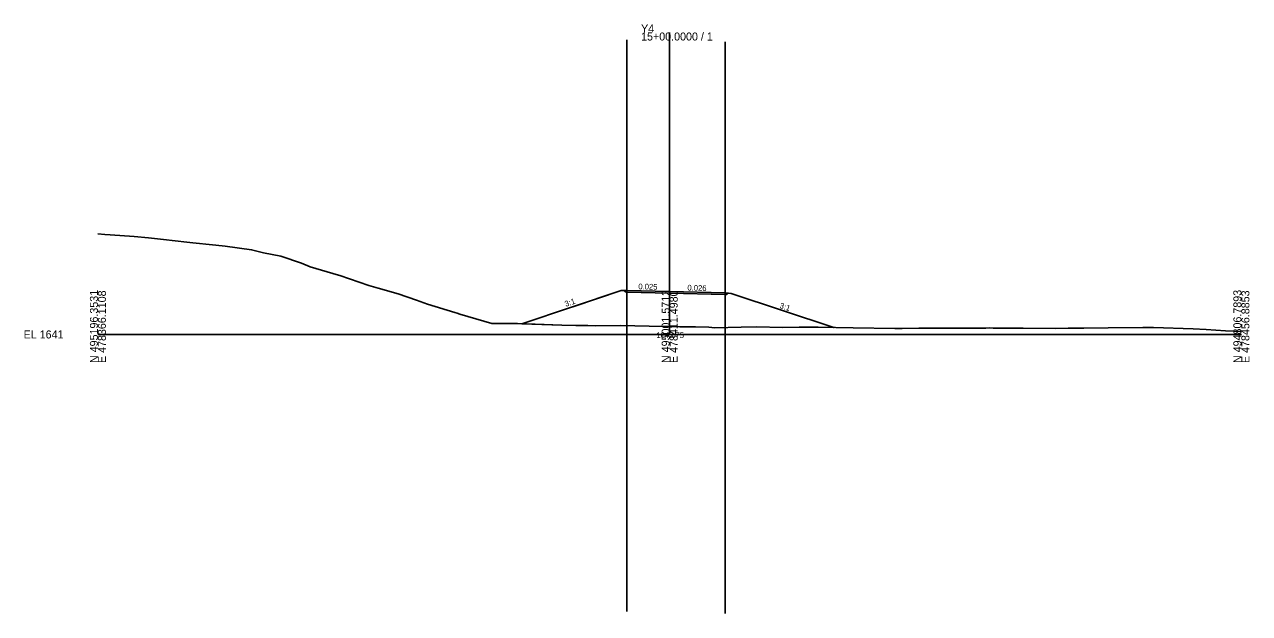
# Model space of a CAD drawing. Extents: x -26 to 403, y -10 to 5108.
# Drawn here: x -25.7 to 402.8, y 4902.4 to 5108.4 of the extents above; entities that cross this region are included whole.
import ezdxf

# ---------------------------------------------------------------- set-up
doc = ezdxf.new("R2010")
doc.units = 0
for name, color, linetype in [('Exist Cross Section Cell', 7, 'Continuous'), ('Exist XS Center Line Elevation Label', 7, 'Continuous'), ('Exist XS Ground Line', 7, 'Continuous'), ('Prop XS Dump Level', 7, 'Continuous'), ('Prop XS Earthwork Shape', 7, 'Continuous'), ('Prop XS EOT Tick Mark', 7, 'Continuous'), ('Prop XS Finish Grade', 7, 'Continuous'), ('Prop XS Finish Grade Earthwork', 7, 'Continuous'), ('Prop XS Finish Grade Pavement', 7, 'Continuous'), ('Prop XS Hydro Fill Slope Data', 7, 'Continuous'), ('Prop XS Pvmt Edge Slope', 7, 'Continuous'), ('Prop XS SE Text', 7, 'Continuous'), ('Prop XS Shoulder Borrow Shape', 7, 'Continuous'), ('Prop XS Side Slope Text', 7, 'Continuous'), ('Prop XS Subgrade Earthwork', 7, 'Continuous'), ('Scratch_Level_1', 7, 'Continuous')]:
    doc.layers.add(name, color=color, linetype=linetype)

msp = doc.modelspace()

# ---------------------------------------------------------------- linework, layer by layer
at = {"layer": 'Exist Cross Section Cell'}
for p, q in [((200, 5000), (200, 5105.64)), ((0, 5000), (200, 5000)), ((200, 5000), (400, 5000))]:
    msp.add_line(p, q, dxfattribs=at)
at = {"layer": 'Exist XS Ground Line'}
msp.add_lwpolyline([(0, 5035.21), (2.37, 5035.02), (4.31, 5034.82), (12.64, 5034.27), (17.7, 5033.79), (22.91, 5033.19), (31.09, 5032.33), (33.18, 5032.1), (40.08, 5031.36), (43.45, 5030.99), (44.48, 5030.86), (53.72, 5029.62), (57.87, 5028.57), (63.99, 5027.34), (71.26, 5024.89), (74.26, 5023.68), (84.15, 5020.79), (84.65, 5020.64), (94.8, 5017.07), (98.04, 5016.22), (105.07, 5014.16), (111.43, 5011.96), (115.34, 5010.58), (124.81, 5007.65), (125.61, 5007.4), (126.55, 5007.1), (137.8, 5003.84), (146.72, 5003.81), (162.3, 5003.28), (167.21, 5003.19), (167.78, 5003.17), (171.37, 5003.13), (174.08, 5003.05), (182.96, 5003.1), (197.77, 5002.78), (198.45, 5002.77), (200, 5002.75), (203.51, 5002.72), (209.02, 5002.62), (213.69, 5002.57), (215.78, 5002.28), (224.97, 5002.54), (230.49, 5002.66), (239.49, 5002.48), (245.32, 5002.6), (249.52, 5002.58), (251.96, 5002.51), (264.23, 5002.28), (278.82, 5002.08), (280.3, 5002.09), (281.3, 5002.09), (287.2, 5002.21), (309.84, 5002.25), (310.55, 5002.2), (312.01, 5002.26), (313.18, 5002.25), (323.67, 5002.18), (335.11, 5002.1), (339.38, 5002.17), (340.67, 5002.19), (342.31, 5002.23), (344.83, 5002.24), (353.41, 5002.35), (365.53, 5002.44), (369.26, 5002.47), (383.17, 5002.01), (387.67, 5001.79), (394.41, 5001.32), (400, 5001.01)], dxfattribs=at)
at = {"layer": 'Prop XS Dump Level'}
for p in [(184.99, 5015.41), (219.36, 5014.54)]:
    msp.add_line(p, (200, 5015.03), dxfattribs=at)
at = {"layer": 'Prop XS Earthwork Shape'}
msp.add_lwpolyline([(239.49, 5002.48), (245.32, 5002.6), (249.52, 5002.58), (251.96, 5002.51), (257.46, 5002.41), (221.55, 5014.38), (220.49, 5014.46), (219.97, 5013.98), (219.36, 5014), (200, 5014.45), (184.99, 5014.8), (184.99, 5014.87), (184.46, 5014.89), (183.97, 5015.38), (182.99, 5015.35), (148.25, 5003.76), (162.3, 5003.28), (167.21, 5003.19), (167.78, 5003.17), (171.37, 5003.13), (174.08, 5003.05), (182.96, 5003.1), (197.77, 5002.78), (198.45, 5002.77), (200, 5002.75), (203.51, 5002.72), (209.02, 5002.62), (213.69, 5002.57), (215.78, 5002.28), (224.97, 5002.54), (230.49, 5002.66)], close=True, dxfattribs=at)
at = {"layer": 'Prop XS EOT Tick Mark'}
for p, q in [((184.99, 5015.41), (184.99, 5016.41)), ((219.36, 5014.54), (219.36, 5015.54))]:
    msp.add_line(p, q, dxfattribs=at)
at = {"layer": 'Prop XS Finish Grade'}
for p, q in [((184.99, 5015.41), (183.97, 5015.38)), ((219.36, 5014.54), (220.49, 5014.46))]:
    msp.add_line(p, q, dxfattribs=at)
at = {"layer": 'Prop XS Finish Grade Earthwork'}
for p, q in [((182.99, 5015.34), (148.25, 5003.76)), ((183.97, 5015.38), (182.99, 5015.35)), ((220.49, 5014.46), (221.55, 5014.38)), ((221.55, 5014.38), (257.46, 5002.41))]:
    msp.add_line(p, q, dxfattribs=at)
at = {"layer": 'Prop XS Finish Grade Pavement'}
for p, q in [((184.99, 5015.41), (200, 5015.03)), ((200, 5015.03), (219.36, 5014.54))]:
    msp.add_line(p, q, dxfattribs=at)
at = {"layer": 'Prop XS Hydro Fill Slope Data'}
msp.add_line((182.99, 5015.35), (166.13, 5009.72), dxfattribs=at)
at = {"layer": 'Prop XS Pvmt Edge Slope'}
for p, q in [((184.99, 5015.41), (184.46, 5014.89)), ((219.36, 5014.54), (219.97, 5013.98))]:
    msp.add_line(p, q, dxfattribs=at)
at = {"layer": 'Prop XS Shoulder Borrow Shape'}
for points in [[(184.99, 5015.41), (183.97, 5015.38), (184.46, 5014.89)], [(219.36, 5014.54), (220.49, 5014.46), (219.97, 5013.98)]]:
    msp.add_lwpolyline(points, close=True, dxfattribs=at)
at = {"layer": 'Prop XS Subgrade Earthwork'}
for p, q in [((184.46, 5014.89), (183.97, 5015.38)), ((184.99, 5014.87), (184.46, 5014.89)), ((184.99, 5014.8), (184.99, 5014.87)), ((200, 5014.45), (184.99, 5014.8)), ((219.36, 5014), (200, 5014.45)), ((219.36, 5014), (219.97, 5013.98)), ((219.97, 5013.98), (220.49, 5014.46))]:
    msp.add_line(p, q, dxfattribs=at)
at = {"layer": 'Scratch_Level_1'}
for p, q in [((184.99, 5103.05), (184.99, 4903.05)), ((219.36, 5102.38), (219.36, 4902.38))]:
    msp.add_line(p, q, dxfattribs=at)

# ---------------------------------------------------------------- texts
at = {"layer": 'Exist Cross Section Cell'}
for s, p in [('Y4', (190, 5105.64)), ('15+00.0000 / 1', (190, 5102.84)), ('EL 1641', (-26, 4998.6))]:
    msp.add_text(s, height=2.8, dxfattribs=at).set_placement(p)
for s, p in [('N 495196.3531', (0, 4990)), ('E 478366.1108', (2.8, 4990)), ('N 495001.5712', (200, 4990)), ('E 478411.4980', (202.8, 4990)), ('N 494806.7893', (400, 4990)), ('E 478456.8853', (402.8, 4990))]:
    msp.add_text(s, height=2.8, rotation=90, dxfattribs=at).set_placement(p)
at = {"layer": 'Exist XS Center Line Elevation Label'}
msp.add_text('1643.75', height=2, dxfattribs=at).set_placement((195.33, 4998.75))
at = {"layer": 'Prop XS Dump Level'}
for p in [(182.99, 5015.31), (221.55, 5014.34)]:
    msp.add_text('Case1', height=0.04, dxfattribs=at).set_placement(p)
at = {"layer": 'Prop XS SE Text'}
for s, p in [('0.025', (189.02, 5015.81)), ('0.026', (206.19, 5015.37))]:
    msp.add_text(s, height=2, rotation=358.5393, dxfattribs=at).set_placement(p)
at = {"layer": 'Prop XS Side Slope Text'}
for rotation, p in [(18.4349, (163.67, 5009.66)), (341.5651, (238.3, 5009.29))]:
    msp.add_text('3:1', height=2, rotation=rotation, dxfattribs=at).set_placement(p)

doc.saveas('drawing.dxf')
